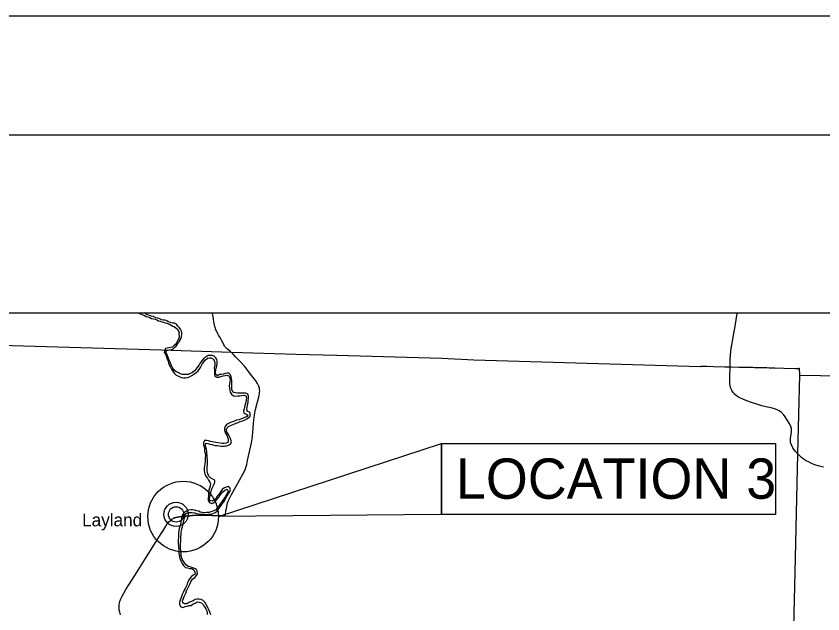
# Model space of a CAD drawing. Extents: x -6.3 to 34, y 0 to 22.
# Drawn here: x 2.176 to 5.581, y 19.479 to 22 of the extents above; entities that cross this region are included whole.
import ezdxf

# ---------------------------------------------------------------- set-up
doc = ezdxf.new("R2010")
doc.units = 0
for name, color, linetype in [('BR_P_Gen_Text', 7, 'Continuous'), ('Default', 7, 'Continuous'), ('GM_X_County', 7, 'Continuous'), ('GM_X_County_Road', 7, 'Continuous'), ('GM_X_Major_River', 7, 'Continuous'), ('GM_X_State_Route', 7, 'Continuous'), ('GM_X_Township', 7, 'Continuous'), ('GM_X_Unincorporated', 7, 'Continuous'), ('GM_X_Unincorporated_Location', 7, 'Continuous'), ('GM_X_Unincorporated_Text', 7, 'Continuous'), ('SH_Border', 7, 'Continuous'), ('SH_Cut_Line', 7, 'Continuous'), ('SH_Text', 7, 'Continuous')]:
    doc.layers.add(name, color=color, linetype=linetype)

msp = doc.modelspace()

# ---------------------------------------------------------------- linework, layer by layer
at = {"layer": 'BR_P_Gen_Text'}
for points in [[(3.9716, 20.1977), (3.9716, 19.8975), (3.0302, 19.8891)], [(3.9716, 20.1977), (5.3803, 20.1977), (5.3803, 19.8975), (3.9716, 19.8975)]]:
    msp.add_lwpolyline(points, close=True, dxfattribs=at)
at = {"layer": 'Default'}
msp.add_circle((2.8812, 19.8891), 0.149, dxfattribs=at)
at = {"layer": 'GM_X_County'}
msp.add_lwpolyline([(5.4835, 20.4857), (5.92, 20.4781), (6.6339, 20.4679), (6.6359, 20.4682), (6.6378, 20.4682), (6.6401, 20.4681), (6.6424, 20.4681), (6.6467, 20.4681), (6.649, 20.4681), (6.6511, 20.4684), (6.6531, 20.4689), (6.6549, 20.4698), (6.6565, 20.4711), (7.387, 20.4633), (8.02, 20.4602), (8.6692, 20.445), (8.712, 20.4444)], dxfattribs=at)
at = {"layer": 'GM_X_County_Road'}
msp.add_line((2.9555, 19.8955), (2.9541, 19.8955), dxfattribs=at)
for points in [[(2.9541, 19.8955), (2.95, 19.8954), (2.921, 19.893), (2.9092, 19.8916), (2.8933, 19.8902), (2.8812, 19.8891), (2.8761, 19.8888), (2.866, 19.8878), (2.857, 19.8866), (2.8505, 19.885), (2.8441, 19.8832), (2.8389, 19.8809)], [(3.0568, 19.8919), (3.0037, 19.8942), (2.9664, 19.8956), (2.9555, 19.8955)]]:
    msp.add_lwpolyline(points, dxfattribs=at)
at = {"layer": 'GM_X_Major_River'}
for p, q in [((2.8109, 20.5896), (2.8034, 20.5898)), ((2.8034, 20.5898), (2.8107, 20.5895))]:
    msp.add_line(p, q, dxfattribs=at)
for points in [[(2.6897, 20.7482), (2.6903, 20.7481), (2.6973, 20.7455), (2.7043, 20.7432), (2.7115, 20.7403), (2.7191, 20.7373), (2.7256, 20.7329), (2.7326, 20.7321), (2.7403, 20.7285), (2.7479, 20.7252), (2.7554, 20.7236), (2.7626, 20.7213), (2.7696, 20.719), (2.7766, 20.7151), (2.7836, 20.7131), (2.7907, 20.7105), (2.7979, 20.7098), (2.8054, 20.7069), (2.8124, 20.7044), (2.8228, 20.7005), (2.8301, 20.6959), (2.8371, 20.6928), (2.8438, 20.6902), (2.8513, 20.6845), (2.8578, 20.6799), (2.8607, 20.6729), (2.8636, 20.6659), (2.8628, 20.6586), (2.8642, 20.6518), (2.8637, 20.6453), (2.8616, 20.6378), (2.857, 20.63), (2.8537, 20.6232), (2.8498, 20.6165), (2.8421, 20.6094), (2.8354, 20.6034), (2.8279, 20.6029), (2.8211, 20.6008), (2.8139, 20.5997), (2.8066, 20.5974), (2.8034, 20.5898)], [(2.829, 20.5922), (2.8315, 20.593), (2.8385, 20.5962), (2.8447, 20.6027), (2.8517, 20.6084), (2.8555, 20.6149), (2.8599, 20.6214), (2.865, 20.6282), (2.8689, 20.635), (2.8728, 20.6423), (2.8738, 20.6488), (2.8755, 20.6571), (2.8758, 20.6649), (2.8744, 20.6719), (2.8698, 20.6799), (2.864, 20.6869), (2.8575, 20.6934), (2.8523, 20.7014), (2.8448, 20.705), (2.8368, 20.7055), (2.8274, 20.7081), (2.8184, 20.7104), (2.8119, 20.7145), (2.8051, 20.7171), (2.7981, 20.7173), (2.7909, 20.7191), (2.7828, 20.7227), (2.7743, 20.7255), (2.7657, 20.727), (2.7553, 20.7332), (2.7468, 20.735), (2.7395, 20.7371), (2.7315, 20.7407), (2.7247, 20.7427), (2.7178, 20.7482)], [(2.8034, 20.5898), (2.8017, 20.5874), (2.8011, 20.5819), (2.8035, 20.5783), (2.808, 20.5707), (2.8137, 20.553)], [(2.8194, 20.5561), (2.8186, 20.558), (2.815, 20.5673), (2.8116, 20.5759), (2.8084, 20.5817), (2.8109, 20.5896)], [(2.8107, 20.5895), (2.8222, 20.5927), (2.829, 20.5922)], [(3.0338, 20.187), (3.0408, 20.1865), (3.0499, 20.1868), (3.0566, 20.1871), (3.0633, 20.1877), (3.0727, 20.1898), (3.0814, 20.1945), (3.0845, 20.2039), (3.0829, 20.2135), (3.0797, 20.2215), (3.075, 20.2298), (3.0696, 20.2391), (3.0643, 20.2482), (3.0635, 20.257), (3.0663, 20.2637), (3.0738, 20.2708), (3.0808, 20.2734), (3.0878, 20.2758), (3.0947, 20.2784), (3.1048, 20.2829), (3.1139, 20.2866), (3.1219, 20.2905), (3.1317, 20.2929), (3.1395, 20.2958), (3.1493, 20.3008), (3.156, 20.305), (3.164, 20.3125), (3.1637, 20.3219), (3.1619, 20.3294), (3.1528, 20.3327), (3.1494, 20.3402), (3.1509, 20.3491), (3.1526, 20.3576), (3.1542, 20.3652), (3.1549, 20.3719), (3.1556, 20.3784), (3.1566, 20.3872), (3.1568, 20.3966), (3.1542, 20.4051), (3.1454, 20.409), (3.1363, 20.4097), (3.1283, 20.4099), (3.1189, 20.4096), (3.1107, 20.4098), (3.1016, 20.4106), (3.0951, 20.4129), (3.0886, 20.4211), (3.0867, 20.4281), (3.0859, 20.4367), (3.0861, 20.444), (3.0863, 20.4533), (3.0858, 20.4626), (3.0833, 20.479), (3.0812, 20.4875), (3.0739, 20.4942), (3.0672, 20.4947), (3.0584, 20.4931), (3.0501, 20.4905), (3.0426, 20.4878), (3.0349, 20.4878), (3.0255, 20.4828), (3.0185, 20.489), (3.018, 20.4976), (3.0189, 20.5067), (3.021, 20.5155), (3.0238, 20.5256), (3.025, 20.5342), (3.0247, 20.5433), (3.0239, 20.5511), (3.0189, 20.5588), (3.0114, 20.566), (3.0031, 20.5691), (2.995, 20.5691), (2.986, 20.568), (2.9775, 20.5633), (2.9684, 20.557), (2.961, 20.5479), (2.9545, 20.539), (2.9481, 20.5296), (2.9427, 20.5216), (2.936, 20.5119), (2.9288, 20.5036), (2.92, 20.497), (2.9112, 20.4926), (2.9027, 20.4886), (2.8921, 20.4881), (2.8843, 20.4885), (2.8776, 20.489), (2.8687, 20.4913), (2.8604, 20.4965), (2.8516, 20.4998), (2.8435, 20.5073), (2.8375, 20.5158), (2.8336, 20.5238), (2.8291, 20.5326), (2.826, 20.5409), (2.8221, 20.5489), (2.8194, 20.5561)], [(2.8137, 20.553), (2.8182, 20.545), (2.8198, 20.5357), (2.8237, 20.5269), (2.8271, 20.5189), (2.8313, 20.5103), (2.8368, 20.5018), (2.8426, 20.494), (2.8509, 20.486), (2.8587, 20.4824), (2.8673, 20.4783), (2.8743, 20.4755), (2.882, 20.4745), (2.8909, 20.4746), (2.8999, 20.4759), (2.9085, 20.4788), (2.9177, 20.4848), (2.9265, 20.4903), (2.9358, 20.4969), (2.9436, 20.5018), (2.9487, 20.5097), (2.9536, 20.5175), (2.959, 20.5263), (2.9634, 20.5344), (2.968, 20.5412), (2.9744, 20.5495), (2.9832, 20.5571), (2.9915, 20.5587), (2.9998, 20.5585), (3.0086, 20.5531), (3.0131, 20.5437), (3.0141, 20.5362), (3.0142, 20.5274), (3.0124, 20.5167), (3.0135, 20.5077), (3.0138, 20.4994), (3.0131, 20.4905), (3.0149, 20.4817), (3.023, 20.4774), (3.0313, 20.4774), (3.0401, 20.4806), (3.0494, 20.4835), (3.0579, 20.4848), (3.0657, 20.4859), (3.0743, 20.4823), (3.0782, 20.4743), (3.0798, 20.4655), (3.0783, 20.4569), (3.076, 20.4486), (3.075, 20.44), (3.0769, 20.4307), (3.0777, 20.4221), (3.0788, 20.4135), (3.0853, 20.405), (3.0936, 20.3991), (3.1022, 20.3973), (3.1112, 20.3979), (3.12, 20.3985), (3.1283, 20.3993), (3.1366, 20.4011), (3.1457, 20.3989), (3.1481, 20.3903), (3.1473, 20.3817), (3.1461, 20.3739), (3.1443, 20.3656), (3.1418, 20.3578), (3.1395, 20.35), (3.1379, 20.3435), (3.1362, 20.3337), (3.1375, 20.3248), (3.1458, 20.322), (3.1541, 20.3166), (3.1487, 20.3096), (3.1399, 20.3072), (3.1319, 20.303), (3.1234, 20.2996), (3.1154, 20.297), (3.1068, 20.2954), (3.0975, 20.2919), (3.0898, 20.289), (3.0812, 20.2856), (3.0719, 20.2814), (3.0634, 20.277), (3.0577, 20.2694), (3.056, 20.2629), (3.0555, 20.2549), (3.0563, 20.2466), (3.0605, 20.2388), (3.067, 20.2297), (3.0699, 20.2207), (3.0715, 20.2121), (3.0705, 20.2033), (3.0622, 20.1991), (3.0542, 20.1978), (3.0457, 20.1967), (3.0366, 20.1987), (3.0273, 20.1999), (3.019, 20.2022)], [(3.019, 20.2022), (3.0122, 20.2032), (3.0039, 20.2048), (2.9964, 20.2065), (2.9884, 20.2083), (2.9803, 20.2096), (2.9712, 20.21), (2.9664, 20.2004), (2.9667, 20.1913), (2.9696, 20.183), (2.9706, 20.1745), (2.9717, 20.1654), (2.9741, 20.1563), (2.9747, 20.1472), (2.9745, 20.1382), (2.9745, 20.1299), (2.9743, 20.1208), (2.9725, 20.1114), (2.971, 20.1026), (2.97, 20.0932), (2.9703, 20.0844), (2.9714, 20.0756), (2.9725, 20.0689), (2.9772, 20.0593), (2.9837, 20.0507), (2.9884, 20.043), (2.9939, 20.0337), (2.9958, 20.0267), (2.9948, 20.0176), (2.992, 20.0095), (2.9889, 20.0002), (2.9876, 19.9913), (2.9885, 19.9838), (2.9877, 19.9752), (2.9865, 19.9659), (2.9865, 19.9568), (2.992, 19.9488), (3.0008, 19.9442), (3.0091, 19.9476), (3.0169, 19.9541), (3.0246, 19.9625), (3.0315, 19.9713), (3.0362, 19.9778), (3.0411, 19.9844), (3.0485, 19.9935), (3.0573, 20.0008), (3.0666, 20.0047), (3.0713, 19.9967), (3.0688, 19.9902), (3.0636, 19.9816), (3.0582, 19.9723), (3.0526, 19.9637), (3.0464, 19.9548), (3.0415, 19.9483), (3.0358, 19.9397), (3.031, 19.9332), (3.0245, 19.9241), (3.0171, 19.916), (3.007, 19.9115), (2.9979, 19.9096), (2.9891, 19.9062), (2.9798, 19.9059), (2.9707, 19.9056), (2.9617, 19.9058), (2.9531, 19.9081), (2.9466, 19.9114), (2.9378, 19.914), (2.9287, 19.916), (2.9207, 19.9173), (2.9137, 19.9172), (2.9038, 19.9156), (2.8948, 19.9122), (2.8862, 19.9072), (2.8798, 19.8989), (2.8757, 19.89), (2.8739, 19.8807), (2.8732, 19.8739), (2.8719, 19.8654), (2.8697, 19.8563), (2.8669, 19.8474), (2.8646, 19.8386), (2.8623, 19.8292), (2.8613, 19.8201), (2.8613, 19.8108), (2.8611, 19.8015), (2.8607, 19.7921), (2.8602, 19.7843), (2.8605, 19.7742), (2.8608, 19.7672), (2.8613, 19.7597), (2.8622, 19.7509), (2.8622, 19.7423), (2.8633, 19.733), (2.8654, 19.7247), (2.8657, 19.7179), (2.8691, 19.7091), (2.8733, 19.7003), (2.8767, 19.6913), (2.8827, 19.6827), (2.8908, 19.6747), (2.8999, 19.6727)], [(2.9102, 19.6766), (2.9022, 19.6792), (2.8941, 19.6851), (2.8863, 19.6939), (2.8813, 19.7019), (2.8769, 19.7094), (2.8742, 19.72), (2.8729, 19.7268), (2.8721, 19.7335), (2.8715, 19.7408), (2.8707, 19.7478), (2.8702, 19.7564), (2.8699, 19.7665), (2.8703, 19.7761), (2.8711, 19.7859), (2.8708, 19.7953), (2.871, 19.8041), (2.872, 19.8137), (2.8732, 19.8226), (2.8742, 19.8303), (2.8757, 19.8376), (2.8778, 19.8452), (2.8795, 19.8517), (2.8818, 19.861), (2.8859, 19.8782), (2.8884, 19.8873), (2.8902, 19.8958), (2.8956, 19.9036), (2.9052, 19.9068), (2.9197, 19.9069), (2.9285, 19.9043), (2.9378, 19.9023), (2.9456, 19.9008), (2.9544, 19.8995), (2.9612, 19.8991), (2.9713, 19.8989), (2.9819, 19.8984), (2.9885, 19.8995), (2.9971, 19.8998), (3.003, 19.9013), (3.0111, 19.9031), (3.0157, 19.9063), (3.0243, 19.9124), (3.0292, 19.9192), (3.0362, 19.9283), (3.0411, 19.9353), (3.0454, 19.9426), (3.0526, 19.9515), (3.0567, 19.9582), (3.0611, 19.9666), (3.0662, 19.9762), (3.0727, 19.9861), (3.0786, 19.9947), (3.0811, 20.0025), (3.0782, 20.011), (3.0704, 20.0154), (3.0622, 20.0125), (3.0529, 20.0093), (3.0461, 20.0033), (3.0392, 19.9929), (3.032, 19.9828), (3.0238, 19.9739), (3.0199, 19.9656), (3.0111, 19.9582), (3.0021, 19.9538), (2.9943, 19.9566), (2.9924, 19.9654), (2.994, 19.9729), (2.9962, 19.9833), (2.9993, 19.9953), (3.0011, 20.0026), (3.0039, 20.0096), (3.0075, 20.0171), (3.0121, 20.0257), (3.0149, 20.0348), (3.0141, 20.0431), (3.0058, 20.0472), (2.9972, 20.0516), (2.9899, 20.0596), (2.9852, 20.0692), (2.9836, 20.0759), (2.9825, 20.0827), (2.9822, 20.0904), (2.9824, 20.0993), (2.9834, 20.1071), (2.9833, 20.1294), (2.983, 20.1372), (2.9819, 20.1457), (2.9816, 20.1545), (2.9808, 20.1626), (2.9795, 20.1735), (2.9771, 20.1818), (2.9747, 20.1908), (2.9765, 20.1992), (2.9853, 20.1979), (2.9941, 20.1951), (3.0019, 20.1925), (3.0099, 20.191), (3.0175, 20.1895), (3.0242, 20.1883), (3.0338, 20.187)], [(2.8999, 19.6727), (2.9092, 19.6707), (2.9178, 19.6697), (2.9266, 19.6638), (2.9303, 19.6552), (2.9314, 19.6469), (2.9236, 19.6419), (2.9161, 19.6362), (2.9074, 19.6268), (2.9038, 19.62), (2.8999, 19.6107), (2.8969, 19.6003), (2.8941, 19.5938), (2.8889, 19.5852), (2.8859, 19.5784), (2.8815, 19.5688), (2.8774, 19.5599), (2.8738, 19.5506), (2.8713, 19.5441), (2.8685, 19.5368), (2.8654, 19.5272), (2.8654, 19.5186), (2.8709, 19.5085), (2.8798, 19.506), (2.8893, 19.5097), (2.8976, 19.5115), (2.9067, 19.5134), (2.915, 19.5137), (2.9227, 19.5207), (2.9315, 19.5239), (2.9403, 19.5291), (2.9483, 19.5287), (2.9579, 19.5251), (2.9657, 19.5186), (2.9717, 19.508), (2.9767, 19.4995), (2.9806, 19.4912), (2.9825, 19.4824), (2.9828, 19.4757)], [(2.9976, 19.4747), (2.9939, 19.4853), (2.9905, 19.4931), (2.9873, 19.5016), (2.9839, 19.5089), (2.9776, 19.5187), (2.9721, 19.5275), (2.9656, 19.535), (2.9565, 19.5396), (2.9482, 19.5409), (2.9415, 19.5411), (2.9324, 19.5387), (2.9231, 19.5332), (2.905, 19.5274), (2.8963, 19.5214), (2.8869, 19.5211), (2.8802, 19.5252), (2.8786, 19.5343), (2.8819, 19.5431), (2.8847, 19.5514), (2.8875, 19.5579), (2.8919, 19.5665), (2.8952, 19.5754), (2.8996, 19.5837), (2.9034, 19.5925), (2.9088, 19.6035), (2.9144, 19.6165), (2.9203, 19.6251), (2.9304, 19.6316), (2.9379, 19.6402), (2.9412, 19.6475), (2.9399, 19.6586), (2.9354, 19.6669), (2.9263, 19.6718), (2.9172, 19.6743), (2.9102, 19.6766)]]:
    msp.add_lwpolyline(points, dxfattribs=at)
at = {"layer": 'GM_X_State_Route'}
for p, q in [((2.9541, 19.8955), (2.9555, 19.8955)), ((2.7924, 19.824), (2.7949, 19.8281))]:
    msp.add_line(p, q, dxfattribs=at)
for points in [[(3.0845, 20.5809), (3.0824, 20.5831), (3.0805, 20.5848), (3.0685, 20.5949), (3.0647, 20.5983), (3.0628, 20.6002), (3.0613, 20.6017), (3.0591, 20.6044), (3.0575, 20.6067), (3.0555, 20.6099), (3.0534, 20.6134), (3.0498, 20.6199), (3.0465, 20.6256), (3.0439, 20.6306), (3.0367, 20.644), (3.0334, 20.6503), (3.0309, 20.6547), (3.0281, 20.66), (3.0243, 20.6671), (3.0214, 20.6728), (3.0196, 20.6769), (3.0182, 20.6806), (3.017, 20.684), (3.0161, 20.6867), (3.0151, 20.6912), (3.0139, 20.6969), (3.0124, 20.704), (3.0096, 20.7199), (3.0073, 20.7324), (3.0058, 20.7406), (3.0048, 20.7453), (3.0042, 20.7482)], [(5.1892, 20.5187), (5.1903, 20.5582), (5.1905, 20.5624), (5.1909, 20.5699), (5.1912, 20.5729), (5.1913, 20.5752), (5.1915, 20.5777), (5.1918, 20.5803), (5.1923, 20.5846), (5.1928, 20.589), (5.193, 20.5908), (5.1934, 20.5939), (5.1939, 20.5972), (5.1945, 20.6008), (5.1952, 20.6057), (5.1991, 20.6285), (5.2066, 20.6703), (5.2103, 20.6913), (5.2168, 20.7284), (5.218, 20.7353), (5.2199, 20.7482)], [(3.0568, 19.8919), (3.0593, 19.8987), (3.0617, 19.9134), (3.0634, 19.9235), (3.0667, 19.9383), (3.0687, 19.9471), (3.0714, 19.9544), (3.0746, 19.9623), (3.0849, 19.9819), (3.1032, 20.0143), (3.1341, 20.0704), (3.1411, 20.0833), (3.1448, 20.0916), (3.1473, 20.0997), (3.1494, 20.1082), (3.1532, 20.1255), (3.1692, 20.1997), (3.1727, 20.2171), (3.1744, 20.2304), (3.1757, 20.2444), (3.1778, 20.2821), (3.1792, 20.2961), (3.1823, 20.3184), (3.1868, 20.3409), (3.2013, 20.3996), (3.2033, 20.4106), (3.2041, 20.419), (3.2038, 20.4255), (3.2031, 20.4302), (3.2005, 20.4395), (3.1952, 20.4499), (3.1875, 20.4617), (3.1712, 20.4828), (3.1574, 20.5016), (3.1463, 20.5157), (3.1398, 20.5236), (3.1248, 20.5399), (3.1026, 20.5626), (3.0917, 20.5739), (3.0845, 20.5809)], [(5.2077, 20.4065), (5.2032, 20.4116), (5.1984, 20.4186), (5.1946, 20.4256), (5.1916, 20.4341), (5.1897, 20.4413), (5.1887, 20.4484), (5.1879, 20.4551), (5.1879, 20.4629), (5.1879, 20.4806), (5.1892, 20.5187)], [(5.4741, 20.1549), (5.4659, 20.1638), (5.4547, 20.1794), (5.4479, 20.192), (5.4447, 20.2022), (5.444, 20.2083), (5.444, 20.2135), (5.4447, 20.2204), (5.4477, 20.236), (5.4488, 20.2456), (5.4488, 20.2534), (5.4482, 20.2609), (5.4458, 20.269), (5.442, 20.2784), (5.4294, 20.2984), (5.4215, 20.3095), (5.4141, 20.3196), (5.4059, 20.3277), (5.396, 20.3352), (5.3874, 20.3397), (5.3763, 20.3435), (5.3622, 20.3473), (5.3401, 20.3523), (5.3229, 20.3567), (5.307, 20.3615), (5.2748, 20.3724), (5.2533, 20.3797), (5.2337, 20.3882), (5.2243, 20.3929), (5.2165, 20.3984), (5.2082, 20.406), (5.2077, 20.4065)], [(5.5839, 20.0982), (5.5616, 20.1033), (5.5471, 20.1073), (5.5333, 20.1129), (5.5225, 20.1182), (5.511, 20.1245), (5.4984, 20.133), (5.4911, 20.1389), (5.476, 20.153), (5.4741, 20.1549)], [(2.8389, 19.8809), (2.8441, 19.8832), (2.8505, 19.885), (2.857, 19.8866), (2.866, 19.8878), (2.8761, 19.8888), (2.8812, 19.8891), (2.8933, 19.8902), (2.9092, 19.8916), (2.921, 19.893), (2.95, 19.8954), (2.9541, 19.8955)], [(2.9555, 19.8955), (2.9664, 19.8956), (3.0037, 19.8942), (3.0568, 19.8919)], [(2.7949, 19.8281), (2.8075, 19.8486), (2.814, 19.8582), (2.8193, 19.8655), (2.827, 19.8731), (2.8329, 19.8777), (2.8389, 19.8809)], [(2.6171, 19.4746), (2.6135, 19.4856), (2.6117, 19.4939), (2.6112, 19.4996), (2.6109, 19.509), (2.6117, 19.5202), (2.6138, 19.5309), (2.6174, 19.5423), (2.6231, 19.5538), (2.6398, 19.5812), (2.6773, 19.6404), (2.7196, 19.7074), (2.7673, 19.7844), (2.7888, 19.8181), (2.7924, 19.824)]]:
    msp.add_lwpolyline(points, dxfattribs=at)
at = {"layer": 'GM_X_Township'}
for points in [[(5.4835, 20.4857), (5.4822, 20.515), (5.4812, 20.5144), (5.4805, 20.5141), (5.4793, 20.5135), (5.4783, 20.5131), (5.4771, 20.5128), (5.4755, 20.5126), (5.4728, 20.5125), (5.4654, 20.5127), (5.4165, 20.5143), (5.3782, 20.5153), (5.3655, 20.5156), (5.3549, 20.5157), (5.3445, 20.5159), (5.3279, 20.5163), (5.3216, 20.5165), (5.3131, 20.5168), (5.2987, 20.5171), (5.293, 20.5172), (5.2848, 20.5174), (5.2786, 20.5174), (5.2662, 20.5176), (5.26, 20.5177), (5.242, 20.5179), (5.2262, 20.5183), (5.1937, 20.519), (5.189, 20.5191), (5.1676, 20.5195), (5.1186, 20.5211), (5.0907, 20.5216), (5.0819, 20.5219), (5.0705, 20.5219), (5.0691, 20.5219), (5.0682, 20.5219), (5.0673, 20.5218), (5.0665, 20.5217), (5.0656, 20.5216), (5.0645, 20.5214), (5.0639, 20.5212), (4.1077, 20.5491), (3.973, 20.5559), (3.5297, 20.5688), (3.3562, 20.5723), (3.0844, 20.5813), (2.7882, 20.5904), (2.0609, 20.6117)], [(5.744, 17.0438), (5.416, 17.0563), (5.4167, 17.4435), (5.4213, 17.5947), (5.4235, 17.6147), (5.4294, 17.6869), (5.4295, 17.7099), (5.4292, 17.7145), (5.4319, 17.8288), (5.4325, 17.8683), (5.4365, 17.9173), (5.4377, 17.9213), (5.4415, 18.2713), (5.4477, 18.8585), (5.4506, 19.1327), (5.4634, 19.6528), (5.4758, 20.1533), (5.4835, 20.4857)]]:
    msp.add_lwpolyline(points, dxfattribs=at)
at = {"layer": 'GM_X_Unincorporated'}
for radius in [0.051, 0.0323]:
    msp.add_circle((2.8511, 19.8985), radius, dxfattribs=at)
at = {"layer": 'GM_X_Unincorporated_Location'}
msp.add_line((2.8511, 19.8985), (2.8511, 19.8985), dxfattribs=at)
at = {"layer": 'SH_Border'}
msp.add_lwpolyline([(1.5, 21.5), (33.5, 21.5), (33.5, 0.5), (1.5, 0.5)], close=True, dxfattribs=at)
at = {"layer": 'SH_Cut_Line'}
msp.add_lwpolyline([(0, 0), (34, 0), (34, 22), (0, 22)], close=True, dxfattribs=at)
at = {"layer": 'SH_Text'}
msp.add_lwpolyline([(1.8145, 20.7482), (12.189, 20.7482), (12.189, 9.3884), (1.8145, 9.3884)], close=True, dxfattribs=at)

# ---------------------------------------------------------------- texts
at = {"layer": 'BR_P_Gen_Text'}
msp.add_text('LOCATION 3', height=0.17, dxfattribs=at).set_placement((4.0323, 19.9643))
at = {"layer": 'GM_X_Unincorporated_Text'}
msp.add_text('Layland', height=0.05413, rotation=0, dxfattribs=at).set_placement((2.4546, 19.8479))

doc.saveas('drawing.dxf')
